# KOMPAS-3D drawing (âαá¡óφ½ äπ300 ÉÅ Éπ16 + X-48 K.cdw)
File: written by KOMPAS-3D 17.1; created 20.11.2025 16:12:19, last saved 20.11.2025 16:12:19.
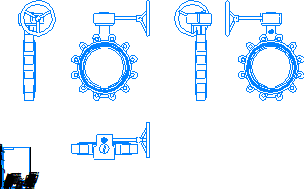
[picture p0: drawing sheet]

Sheet 1: A4, portrait

Title block, sheet 1: name: Гранвэл Ду300; material: Сталь 10  ГОСТ 1050-88; mass: 60,93; sheets: 1; sheet format: A4

Views: Вид 1, Спереди, Проекционный вид 2, Проекционный вид 3, Проекционный вид 4, Проекционный вид 5
Referenced files in \\adlc.lan\data\АДЛ_ПКД\3D-модели\ADL production\Дисковые поворотные затворы ГРАНВЭЛ\с резьбовыми проушинами с китайским редуктором Ру 16\KOMPAS 3D\: Гранвэл Ду300 РП Ру16 + X-48 K.m3d
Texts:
  Andrey
  АДЛ
Dimensions and other numbers on the sheet: 1:1; 1; 60,93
